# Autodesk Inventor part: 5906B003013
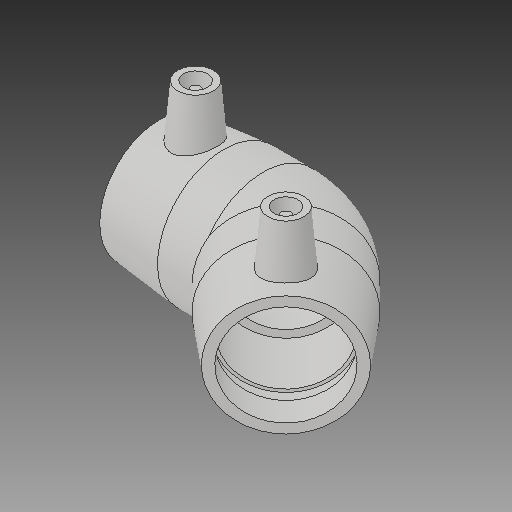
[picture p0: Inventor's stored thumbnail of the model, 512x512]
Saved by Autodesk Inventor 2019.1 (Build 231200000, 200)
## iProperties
Created: 2017-06
Part Number: 5906B003013
Material: Generic
Description: PLASSON 45° ELBOW 1 3/4''
Document SubType Name: Modeling
Designer: KIM
Mass: 55.0731 g
Surface Area: 148.067 cm^2
Volume: 55.0731 cm^3
Density: 1 g/cm^3
Appearance: Default
Author: KIM
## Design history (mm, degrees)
derived "5906B.ipt"
feature "Solid1::5906B.ipt"
tag "TaggingFeature1"
body "Solid1"
other parameters: "d2" = 55.626, "d4" = 26.9875, "d5" = 50.0634, "d8" = 168 deg, "d10" = 17.3736, "d11" = 5.7912, "d14" = 17.6296, "d18" = 42.1, "d19" = 3.52592, "d20" = 168 deg, "d22" = 51.17592, "d23" = 55.626, "d24" = 49.64064, "d29" = 46.736, "d30" = 15, "d31" = 37.7825, "d34" = 5 deg, "d35" = 12, "d39" = 0, "d41" = 4, "d42" = 14, "d43" = 0, "d44" = 9.6, "d45" = 4.8, "d46" = 6, "d47" = 0, "d49" = 42.1, "d50" = 35.785, "d51" = 17.3736, "d52" = 43.434, "d54" = 135 deg, "d65" = 42.1, "d67" = 45 deg, "d71" = 135 deg, "d75" = 2.7813, "d82" = 45 deg, "d83" = 43.434, "d84" = 50.0634, "d86" = 25.0317, "d87" = 135 deg, "d88" = 107.95, "d90" = 43.434, "d91" = 0, "d92" = 43.434, "d93" = 0, "d94" = 135 deg, "d95" = 24.82032, "d98" = 107.95, "d99" = 32.385, "d101" = 3, "d102" = 0, "d103" = 3, "d104" = 0, "d105" = 12.59586, "d106" = 3.14896, "d_" = 42.1, "L_" = 107.95, "L_1" = 43.434, "D_" = 55.626, "A_" = 46.736, "d_2" = 12
